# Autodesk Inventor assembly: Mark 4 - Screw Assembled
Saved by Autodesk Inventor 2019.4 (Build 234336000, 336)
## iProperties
Created: 2020-06
Part Number: Mark 4 - Screw Assembled
Document SubType Name: Assembly
Designer: Administrator
Title: Mark 4 - Screw Assembled v11
Author: Administrator
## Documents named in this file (2)
- c:\worker\convert-fusion-r04\tmp\job-1\729\output\files\0d8d32a3-fb69-47a3-ba5c-0890911299e4\61e1bd03-e7fe-41b3-963b-8646ade5d634.iam
- c:\worker\convert-fusion-r04\tmp\job-1\729\output\files\0d8d32a3-fb69-47a3-ba5c-0890911299e4\Upgraded Screw Harry Edited v16.ipt
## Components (1 placed, 1 different names)
1. Upgraded Screw Harry Edited v16:1
